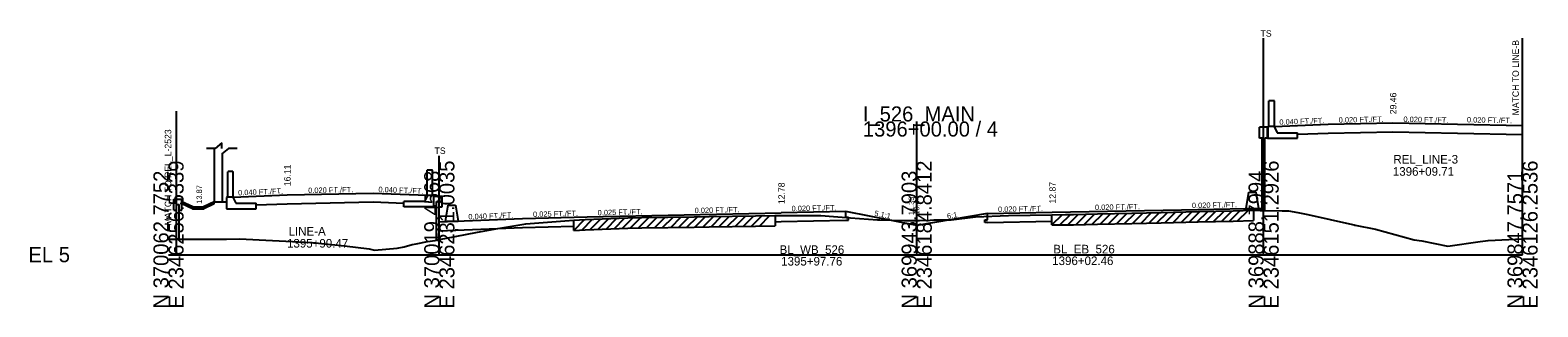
# Model space of a CAD drawing. Extents: x -170 to 2527928, y -10 to 1619750.
# Drawn here: x 1974.3 to 2254.3, y 6990.3 to 7041.7 of the extents above; entities that cross this region are included whole.
import ezdxf

# ---------------------------------------------------------------- set-up
doc = ezdxf.new("R2010")
doc.units = 0
for name, color, linetype in [('Default', 7, 'Continuous'), ('RD_GPK_XS_Cell', 7, 'Continuous'), ('RD_PD_NOISE-WALL-GM', 7, 'Continuous'), ('RD_PD_WallFill', 7, 'Continuous'), ('RD_XS_Base', 7, 'Continuous'), ('RD_XS_EarthShd', 7, 'Continuous'), ('RD_XS_ExGround', 7, 'Continuous'), ('RD_XS_ExPaveRet', 7, 'Continuous'), ('RD_XS_MatchLine', 7, 'Continuous'), ('RD_XS_Pave', 7, 'Continuous'), ('RD_XS_PaveShd', 7, 'Continuous'), ('RD_XS_TieSlope', 7, 'Continuous'), ('RD_XS_TX_Elev_EX', 7, 'Continuous'), ('RD_XS_TX_Elev_PR', 7, 'Continuous'), ('RD_XS_TX_Slope', 7, 'Continuous'), ('RD_XS_TX_Station', 7, 'Continuous')]:
    doc.layers.add(name, color=color, linetype=linetype)

msp = doc.modelspace()

# ---------------------------------------------------------------- linework, layer by layer
at = {"layer": 'Default'}
for p, q in [((2008.63, 7019.74), (2007.05, 7019.74)), ((2009.88, 7020.77), (2008.63, 7019.74)), ((2009.88, 7019.74), (2009.88, 7020.77)), ((2011.13, 7019.74), (2009.88, 7018.71)), ((2012.72, 7019.74), (2011.13, 7019.74))]:
    msp.add_line(p, q, dxfattribs=at)
at = {"layer": 'RD_GPK_XS_Cell'}
for p, q in [((2138.92, 7000), (2138.92, 7024.74)), ((2000, 7000), (2050.28, 7000)), ((2050.28, 7000), (2138.92, 7000)), ((2138.92, 7000), (2203.33, 7000)), ((2203.33, 7000), (2251.41, 7000))]:
    msp.add_line(p, q, dxfattribs=at)
at = {"layer": 'RD_PD_NOISE-WALL-GM'}
for p, q in [((2008.5, 7019.74), (2008.5, 7009.79)), ((2010, 7009.79), (2010, 7018.81)), ((2200.08, 7008.59), (2200.57, 7011.59)), ((2200.57, 7011.59), (2201.91, 7011.59)), ((2201.91, 7011.59), (2202.39, 7008.59)), ((2051.45, 7006.22), (2051.93, 7009.22)), ((2051.93, 7009.22), (2053.27, 7009.22)), ((2053.27, 7009.22), (2053.75, 7006.22)), ((2051.45, 7006.22), (2053.75, 7006.22))]:
    msp.add_line(p, q, dxfattribs=at)
at = {"layer": 'RD_PD_WallFill'}
for p, q in [((2204.33, 7023.82), (2204.33, 7028.58)), ((2205.33, 7028.58), (2204.33, 7028.58)), ((2205.33, 7023.82), (2205.33, 7028.58)), ((2204.21, 7023.82), (2204.04, 7023.66)), ((2205.33, 7023.82), (2204.21, 7023.82)), ((2205.33, 7023.82), (2205.33, 7023.66)), ((2251.41, 7002.92), (2251.41, 7023.98)), ((2202.55, 7021.66), (2202.55, 7023.66)), ((2204.05, 7023.66), (2202.55, 7023.66)), ((2203.05, 7021.66), (2202.55, 7021.66)), ((2203.05, 7008.22), (2203.05, 7021.66)), ((2203.55, 7008.21), (2203.55, 7021.66)), ((2204.05, 7021.66), (2203.55, 7021.66)), ((2204.05, 7021.66), (2204.05, 7023.66)), ((2204.12, 7023.66), (2204.05, 7023.66)), ((2204.05, 7021.66), (2209.62, 7021.66)), ((2204.12, 7021.66), (2204.05, 7021.66)), ((2204.12, 7023.74), (2204.12, 7021.66)), ((2205.33, 7023.66), (2205.83, 7022.66)), ((2205.83, 7022.66), (2209.62, 7022.66)), ((2209.62, 7021.66), (2209.62, 7022.66)), ((2011.08, 7015.46), (2011, 7015.38)), ((2011.92, 7015.46), (2011.08, 7015.46)), ((2011.92, 7015.46), (2012, 7015.38)), ((2048.08, 7015.78), (2048, 7015.7)), ((2048, 7011.03), (2048, 7015.7)), ((2048.08, 7015.78), (2048.92, 7015.78)), ((2048.92, 7015.78), (2049, 7015.7)), ((2049, 7011.03), (2049, 7015.7)), ((2011, 7010.71), (2011, 7015.38)), ((2012, 7010.71), (2012, 7015.38)), ((2001, 7010.29), (2002.5, 7010.29)), ((2001, 7008.29), (2001, 7010.29)), ((2002.5, 7008.29), (2002.5, 7010.29)), ((2010.87, 7010.71), (2010.79, 7010.62)), ((2010.79, 7010.62), (2010.79, 7008.54)), ((2012, 7010.71), (2010.87, 7010.71)), ((2012, 7010.71), (2012, 7010.54)), ((2012, 7010.54), (2012.49, 7009.54)), ((2047.51, 7009.86), (2043.71, 7009.86)), ((2043.71, 7008.86), (2043.71, 7009.86)), ((2048, 7010.86), (2047.51, 7009.86)), ((2048, 7011.03), (2049.13, 7011.03)), ((2048, 7011.03), (2048, 7010.86)), ((2049.13, 7011.03), (2049.29, 7010.86)), ((2049.21, 7010.94), (2049.21, 7008.86)), ((2049.21, 7010.86), (2049.28, 7010.86)), ((2049.28, 7008.86), (2049.28, 7010.86)), ((2049.28, 7010.86), (2050.78, 7010.86)), ((2049.78, 7009.86), (2050.28, 7009.86)), ((2049.78, 7002.71), (2049.78, 7009.86)), ((2050.28, 7002.82), (2050.28, 7009.86)), ((2050.78, 7008.86), (2050.78, 7010.86)), ((2001, 7008.29), (2001.5, 7008.29)), ((2001.5, 7002.9), (2001.5, 7009.29)), ((2001.5, 7009.29), (2002, 7009.29)), ((2002, 7002.9), (2002, 7009.29)), ((2002, 7008.29), (2002.5, 7008.29)), ((2004.5, 7008.87), (2002.5, 7009.79)), ((2004.43, 7008.54), (2002.5, 7009.42)), ((2004.43, 7008.54), (2006.57, 7008.54)), ((2004.5, 7008.87), (2006.5, 7008.87)), ((2008.5, 7009.79), (2006.5, 7008.87)), ((2008.5, 7009.42), (2006.57, 7008.54)), ((2008.5, 7009.42), (2008.5, 7009.79)), ((2010.79, 7008.54), (2016.29, 7008.54)), ((2012.49, 7009.54), (2016.29, 7009.54)), ((2016.29, 7008.54), (2016.29, 7009.54)), ((2049.28, 7008.86), (2043.71, 7008.86)), ((2049.21, 7008.86), (2049.28, 7008.86)), ((2049.28, 7008.86), (2049.78, 7008.86)), ((2050.28, 7008.86), (2050.78, 7008.86)), ((2200.08, 7008.59), (2203.05, 7008.59))]:
    msp.add_line(p, q, dxfattribs=at)
at = {"layer": 'RD_XS_Base'}
for p, q in [((2209.62, 7022.36), (2215.33, 7022.59)), ((2215.33, 7022.59), (2227.33, 7022.83)), ((2227.33, 7022.83), (2239.33, 7022.59)), ((2239.33, 7022.59), (2251.41, 7022.35)), ((2016.29, 7009.24), (2022, 7009.47)), ((2022, 7009.47), (2038, 7009.79)), ((2038, 7009.79), (2043.71, 7009.56)), ((2125.75, 7006.88), (2125.75, 7008.02)), ((2152.08, 7006.5), (2152.08, 7007.63)), ((2200.08, 7008.22), (2200.08, 7008.59)), ((2050.28, 7004.44), (2050.28, 7006.08)), ((2050.28, 7004.44), (2065.75, 7005.06)), ((2053.75, 7004.58), (2053.25, 7004.56)), ((2065.75, 7005.06), (2075.24, 7005.3)), ((2112.62, 7006.12), (2113.75, 7006.14)), ((2113.75, 7006.14), (2125.75, 7006.38)), ((2126.25, 7006.89), (2125.75, 7006.88)), ((2125.75, 7006.38), (2126.25, 7006.39)), ((2126.25, 7006.39), (2126.25, 7006.89)), ((2151.58, 7006.49), (2152.08, 7006.5)), ((2151.58, 7005.99), (2151.58, 7006.49)), ((2152.08, 7006), (2151.58, 7005.99)), ((2152.08, 7006), (2164.01, 7006.24))]:
    msp.add_line(p, q, dxfattribs=at)
at = {"layer": 'RD_XS_EarthShd'}
msp.add_line((2008.5, 7009.79), (2010.79, 7009.79), dxfattribs=at)
at = {"layer": 'RD_XS_ExGround'}
msp.add_lwpolyline([(2000, 7002.9), (2010.77, 7002.91), (2013.2, 7002.92), (2026.64, 7002.25), (2032.69, 7001.63), (2037.26, 7001.09), (2038.22, 7000.84), (2042.44, 7001.21), (2043.75, 7001.48), (2045.21, 7001.89), (2046, 7002.01), (2048.11, 7002.45), (2049.48, 7002.66), (2050.28, 7002.82), (2051.28, 7003.02), (2057.34, 7004.19), (2061.12, 7004.84), (2066.32, 7005.71), (2073.61, 7006.31), (2075.24, 7006.43), (2077.33, 7006.52), (2085.31, 7006.85), (2087.91, 7006.89), (2097.63, 7007.05), (2100.39, 7007.09), (2109.01, 7007.22), (2112.55, 7007.27), (2112.62, 7007.27), (2112.73, 7007.27), (2121.13, 7007.27), (2126.65, 7006.82), (2131.66, 7006.49), (2132.08, 7006.48), (2136.52, 7006.32), (2138.92, 7006.33), (2139.45, 7006.33), (2141.39, 7006.44), (2142.11, 7006.45), (2145.3, 7006.5), (2149.81, 7007.03), (2155.94, 7007.3), (2164.01, 7007.43), (2166.54, 7007.47), (2168.01, 7007.49), (2172.47, 7007.58), (2178.86, 7007.7), (2184.29, 7007.83), (2191.21, 7007.99), (2197.7, 7008.16), (2201.46, 7008.25), (2203.33, 7008.22), (2206.76, 7008.16), (2207.98, 7008.13), (2209.71, 7007.81), (2211.53, 7007.45), (2219.82, 7005.59), (2220.12, 7005.53), (2220.26, 7005.5), (2220.32, 7005.48), (2224.11, 7004.76), (2231.26, 7002.78), (2232.74, 7002.55), (2237.53, 7001.56), (2243.57, 7002.43), (2245.02, 7002.66), (2251.41, 7002.92)], dxfattribs=at)
at = {"layer": 'RD_XS_ExPaveRet'}
for p, q in [((2094.74, 7005.08), (2096.69, 7007.03)), ((2096.24, 7005.11), (2098.19, 7007.06)), ((2097.74, 7005.13), (2099.69, 7007.08)), ((2099.24, 7005.16), (2101.19, 7007.11)), ((2100.74, 7005.18), (2102.68, 7007.13)), ((2102.24, 7005.21), (2104.18, 7007.15)), ((2103.74, 7005.23), (2105.68, 7007.17)), ((2105.24, 7005.25), (2107.18, 7007.2)), ((2106.74, 7005.27), (2108.68, 7007.22)), ((2108.24, 7005.29), (2110.18, 7007.24)), ((2109.74, 7005.32), (2111.68, 7007.26)), ((2112.62, 7007.27), (2112.62, 7005.36)), ((2164.01, 7005.52), (2165.96, 7007.46)), ((2164.01, 7005.52), (2164.01, 7007.43)), ((2165.51, 7005.54), (2167.46, 7007.48)), ((2167.01, 7005.56), (2168.97, 7007.51)), ((2168.51, 7005.58), (2170.47, 7007.54)), ((2170.01, 7005.61), (2171.97, 7007.57)), ((2171.51, 7005.64), (2173.47, 7007.6)), ((2173.01, 7005.67), (2174.97, 7007.63)), ((2174.51, 7005.7), (2176.47, 7007.65)), ((2176.01, 7005.73), (2177.97, 7007.68)), ((2177.51, 7005.76), (2179.47, 7007.71)), ((2179.01, 7005.79), (2180.98, 7007.75)), ((2180.51, 7005.82), (2182.48, 7007.78)), ((2182.01, 7005.86), (2183.98, 7007.82)), ((2183.51, 7005.89), (2185.48, 7007.86)), ((2185.01, 7005.93), (2186.98, 7007.89)), ((2186.51, 7005.96), (2188.48, 7007.93)), ((2188.01, 7006), (2189.98, 7007.96)), ((2189.51, 7006.04), (2191.48, 7008)), ((2191.01, 7006.07), (2192.98, 7008.04)), ((2192.51, 7006.11), (2194.48, 7008.08)), ((2194.01, 7006.15), (2195.98, 7008.11)), ((2195.51, 7006.19), (2197.48, 7008.15)), ((2197.01, 7006.22), (2198.98, 7008.19)), ((2198.51, 7006.26), (2200.48, 7008.22)), ((2201.46, 7008.25), (2201.46, 7006.33)), ((2075.24, 7004.51), (2077.24, 7006.51)), ((2075.24, 7004.51), (2075.24, 7006.43)), ((2075.24, 7004.51), (2077.33, 7004.6)), ((2076.74, 7004.58), (2078.74, 7006.58)), ((2077.33, 7004.6), (2085.31, 7004.93)), ((2078.24, 7004.64), (2080.24, 7006.64)), ((2079.74, 7004.7), (2081.74, 7006.7)), ((2081.24, 7004.76), (2083.24, 7006.77)), ((2082.74, 7004.83), (2084.74, 7006.83)), ((2084.24, 7004.89), (2086.21, 7006.86)), ((2085.31, 7004.93), (2087.91, 7004.97)), ((2085.74, 7004.94), (2087.68, 7006.89)), ((2087.24, 7004.96), (2089.19, 7006.91)), ((2087.91, 7004.97), (2097.63, 7005.13)), ((2088.74, 7004.99), (2090.69, 7006.93)), ((2090.24, 7005.01), (2092.19, 7006.96)), ((2091.74, 7005.03), (2093.69, 7006.98)), ((2093.24, 7005.06), (2095.19, 7007.01)), ((2097.63, 7005.13), (2100.39, 7005.18)), ((2100.39, 7005.18), (2109.01, 7005.31)), ((2109.01, 7005.31), (2112.55, 7005.36)), ((2112.55, 7005.36), (2112.62, 7005.36)), ((2164.01, 7005.52), (2166.54, 7005.55)), ((2166.54, 7005.55), (2168.01, 7005.57)), ((2168.01, 7005.57), (2172.47, 7005.66)), ((2172.47, 7005.66), (2178.86, 7005.78)), ((2178.86, 7005.78), (2184.29, 7005.91)), ((2184.29, 7005.91), (2191.21, 7006.08)), ((2191.21, 7006.08), (2197.7, 7006.24)), ((2197.7, 7006.24), (2201.46, 7006.33))]:
    msp.add_line(p, q, dxfattribs=at)
at = {"layer": 'RD_XS_MatchLine'}
for p, q in [((2203.33, 7000), (2203.33, 7040.2)), ((2251.41, 7000), (2251.41, 7040.2)), ((2001.5, 7000), (2001.5, 7026.65)), ((2050.28, 7000), (2050.28, 7018.39))]:
    msp.add_line(p, q, dxfattribs=at)
at = {"layer": 'RD_XS_Pave'}
for p, q in [((2215.33, 7024.22), (2227.33, 7024.46)), ((2227.33, 7024.46), (2239.33, 7024.22)), ((2022, 7011.11), (2038, 7011.43)), ((2077.75, 7007), (2089.75, 7007.3)), ((2089.75, 7007.3), (2113.75, 7007.78)), ((2164.08, 7007.87), (2188.08, 7008.35)), ((2065.75, 7006.7), (2077.75, 7007))]:
    msp.add_line(p, q, dxfattribs=at)
at = {"layer": 'RD_XS_PaveShd'}
for p, q in [((2205.33, 7023.82), (2215.33, 7024.22)), ((2239.33, 7024.22), (2251.41, 7023.98)), ((2012, 7010.71), (2022, 7011.11)), ((2038, 7011.43), (2048, 7011.03)), ((2125.75, 7008.02), (2113.75, 7007.78)), ((2152.08, 7007.63), (2164.08, 7007.87)), ((2188.08, 7008.35), (2200.08, 7008.59)), ((2050.28, 7006.08), (2065.75, 7006.7))]:
    msp.add_line(p, q, dxfattribs=at)
at = {"layer": 'RD_XS_TieSlope'}
for p, q in [((2138.92, 7005.44), (2125.75, 7008.02)), ((2152.08, 7007.63), (2138.92, 7005.44))]:
    msp.add_line(p, q, dxfattribs=at)

# ---------------------------------------------------------------- texts
at = {"layer": 'RD_GPK_XS_Cell'}
for s, p in [('I_526_MAIN', (2128.92, 7024.74)), ('1396+00.00 / 4', (2128.92, 7021.94)), ('EL 5', (1974, 6998.6))]:
    msp.add_text(s, height=2.8, dxfattribs=at).set_placement(p)
for s, p in [('N 370062.7752', (2000, 6990)), ('E 2346256.5339', (2002.8, 6990)), ('N 370019.4568', (2050.28, 6990)), ('E 2346231.0035', (2053.08, 6990)), ('N 369943.7903', (2138.92, 6990)), ('E 2346184.8412', (2141.72, 6990)), ('N 369888.7994', (2203.33, 6990)), ('E 2346151.2926', (2206.13, 6990)), ('N 369847.7571', (2251.41, 6990)), ('E 2346126.2536', (2254.21, 6990))]:
    msp.add_text(s, height=2.8, rotation=90, dxfattribs=at).set_placement(p)
at = {"layer": 'RD_XS_MatchLine'}
for p in [(2202.77, 7040.49), (2049.4, 7018.71)]:
    msp.add_text('TS', height=1.2, dxfattribs=at).set_placement(p)
for s, p in [('MATCH TO LINE-B', (2250.73, 7025.88)), ('MATCH TO REL_L-2523', (2000.5, 7005.44))]:
    msp.add_text(s, height=1.2, rotation=90, dxfattribs=at).set_placement(p)
at = {"layer": 'RD_XS_TX_Elev_EX'}
msp.add_text('11.33', height=1, rotation=90, dxfattribs=at).set_placement((2138.42, 7007.33))
at = {"layer": 'RD_XS_TX_Elev_PR'}
msp.add_text('10.44', height=1, rotation=90, dxfattribs=at).set_placement((2139.42, 7007.44))
at = {"layer": 'RD_XS_TX_Slope'}
for s, rotation, p in [('0.040 FT./FT.', 2.2906, (2206.28, 7024.11)), ('0.020 FT./FT.', 1.1458, (2217.28, 7024.51)), ('0.020 FT./FT.', 358.8542, (2229.29, 7024.67)), ('0.020 FT./FT.', 358.8542, (2241.08, 7024.58)), ('13.87', 90, (2006.2, 7009.46)), ('0.040 FT./FT.', 357.7094, (2038.96, 7011.64)), ('0.040 FT./FT.', 2.2906, (2012.94, 7011)), ('0.020 FT./FT.', 1.1458, (2025.94, 7011.44)), ('0.020 FT./FT.', 1.1458, (2190.03, 7008.64)), ('0.040 FT./FT.', 2.2906, (2055.69, 7006.54)), ('0.025 FT./FT.', 1.4321, (2067.69, 7006.99)), ('0.025 FT./FT.', 1.4321, (2079.69, 7007.29)), ('0.020 FT./FT.', 1.1458, (2097.69, 7007.71)), ('0.020 FT./FT.', 1.1458, (2115.69, 7008.07)), ('5.1:1', 348.9274, (2131, 7007.24)), ('6:1', 9.4623, (2144.63, 7006.65)), ('0.020 FT./FT.', 1.1458, (2154.03, 7007.92)), ('0.020 FT./FT.', 1.1458, (2172.03, 7008.28))]:
    msp.add_text(s, height=1, rotation=rotation, dxfattribs=at).set_placement(p)
at = {"layer": 'RD_XS_TX_Station'}
for s, p in [(' 29.46', (2227.99, 7025.64)), (' 16.11', (2022.66, 7012.28)), (' 12.78', (2114.41, 7008.95)), (' 12.87', (2164.74, 7009.05))]:
    msp.add_text(s, height=1.2, rotation=90, dxfattribs=at).set_placement(p)
for s, p in [('REL_LINE-3', (2227.43, 7016.92)), ('1396+09.71', (2227.33, 7014.66)), ('LINE-A', (2022.29, 7003.56)), ('1395+90.47', (2022, 7001.31)), ('BL_WB_526', (2113.46, 7000.13)), ('BL_EB_526', (2164.28, 7000.23)), ('1395+97.76', (2113.75, 6997.98)), ('1396+02.46', (2164.08, 6998.07))]:
    msp.add_text(s, height=1.6, dxfattribs=at).set_placement(p)

doc.saveas('drawing.dxf')
